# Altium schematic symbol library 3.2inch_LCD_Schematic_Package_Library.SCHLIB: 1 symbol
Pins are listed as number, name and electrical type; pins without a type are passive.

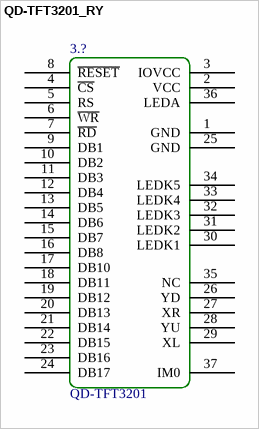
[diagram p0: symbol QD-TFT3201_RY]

## QD-TFT3201_RY
designator 3.?, comment QD-TFT3201
footprint 3.2_37PIN_ILI9341B
pins: 1 GND, 2 VCC, 3 IOVCC, 4 ~{CS}, 5 RS, 6 ~{WR}, 7 ~{RD}, 8 ~{RESET}, 9 DB1, 10 DB2, 11 DB3, 12 DB4, 13 DB5, 14 DB6, 15 DB7, 16 DB8, 17 DB10, 18 DB11, 19 DB12, 20 DB13, 21 DB14, 22 DB15, 23 DB16, 24 DB17, 25 GND, 26 YD, 27 XR, 28 YU, 29 XL, 30 LEDK1, 31 LEDK2, 32 LEDK3, 33 LEDK4, 34 LEDK5, 35 NC, 36 LEDA, 37 IM0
